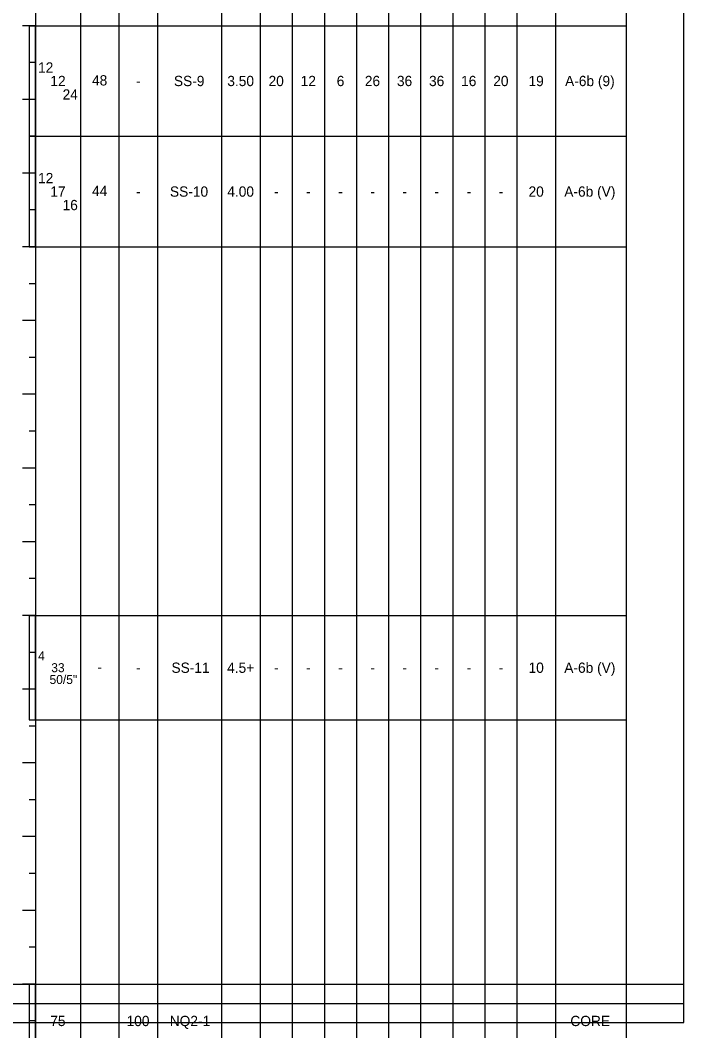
# Model space of a CAD drawing. Extents: x -0.01 to 0.83, y -0.77 to 1.27.
# Drawn here: x 0.403 to 0.833, y -0.03 to 0.625 of the extents above; entities that cross this region are included whole.
import ezdxf

# ---------------------------------------------------------------- set-up
doc = ezdxf.new("R2010")
doc.units = 0

msp = doc.modelspace()

# ---------------------------------------------------------------- linework, layer by layer
for points in [[(0, 0), (0.83333, 0), (0.83333, 1.275), (0, 1.275)], [(0, 0), (0.83333, 0), (0.83333, 1.275), (0, 1.275)], [(0, 0), (0.83333, 0), (0.83333, 1.275), (0, 1.275)], [(0, 0), (0.83333, 0), (0.83333, 1.275), (0, 1.275)], [(0, 0), (0.83333, 0), (0.83333, 1.275), (0, 1.275)], [(0.40833, 0.55008), (0.4125, 0.55008), (0.4125, 0.62183), (0.40833, 0.62183)], [(0.40833, 0.47833), (0.4125, 0.47833), (0.4125, 0.55008), (0.40833, 0.55008)], [(0.40833, 0.1714), (0.4125, 0.1714), (0.4125, 0.23917), (0.40833, 0.23917)], [(0.40833, -0.04783), (0.4125, -0.04783), (0.4125, 0), (0.40833, 0)]]:
    msp.add_lwpolyline(points, close=True)
for points in [[(0.4125, 1.22083), (0.4125, -0.76533)], [(0.4125, 1.22083), (0.4125, -0.76533)], [(0.44167, 1.22083), (0.44167, -0.76533)], [(0.46667, 1.22083), (0.46667, -0.76533)], [(0.49167, 1.22083), (0.49167, -0.76533)], [(0.53333, 1.22083), (0.53333, -0.76533)], [(0.55833, 1.22083), (0.55833, -0.76533)], [(0.6625, 1.22083), (0.6625, -0.76533)], [(0.725, 1.22083), (0.725, -0.76533)], [(0.75, 1.22083), (0.75, -0.76533)], [(0.75, 1.22083), (0.75, -0.76533)], [(0.79583, 1.22083), (0.79583, -0.76533)], [(0.57917, 1.20833), (0.57917, -0.76533)], [(0.6, 1.20833), (0.6, -0.76533)], [(0.62083, 1.20833), (0.62083, -0.76533)], [(0.64167, 1.20833), (0.64167, -0.76533)], [(0.68333, 1.20833), (0.68333, -0.76533)], [(0.70417, 1.20833), (0.70417, -0.76533)], [(0.725, 1.20833), (0.725, -0.76533)], [(0.4125, 0.62183), (0.40417, 0.62183)], [(0.40833, 0.62183), (0.40833, 0.55008)], [(0.40833, 0.62183), (0.4125, 0.62183)], [(0.4125, 0.62183), (0.40833, 0.62183)], [(0.4125, 0.62183), (0.44167, 0.62183)], [(0.44167, 0.62183), (0.46667, 0.62183)], [(0.46667, 0.62183), (0.49167, 0.62183)], [(0.49167, 0.62183), (0.53333, 0.62183)], [(0.53333, 0.62183), (0.55833, 0.62183)], [(0.55833, 0.62183), (0.57917, 0.62183)], [(0.57917, 0.62183), (0.6, 0.62183)], [(0.6, 0.62183), (0.62083, 0.62183)], [(0.62083, 0.62183), (0.64167, 0.62183)], [(0.64167, 0.62183), (0.6625, 0.62183)], [(0.6625, 0.62183), (0.68333, 0.62183)], [(0.68333, 0.62183), (0.70417, 0.62183)], [(0.70417, 0.62183), (0.725, 0.62183)], [(0.725, 0.62183), (0.75, 0.62183)], [(0.75, 0.62183), (0.79583, 0.62183)], [(0.4125, 0.59792), (0.40833, 0.59792)], [(0.4125, 0.574), (0.40417, 0.574)], [(0.4125, 0.574), (0.40833, 0.574)], [(0.40833, 0.55008), (0.4125, 0.55008)], [(0.40833, 0.55008), (0.40833, 0.47833)], [(0.40833, 0.55008), (0.4125, 0.55008)], [(0.4125, 0.55008), (0.40833, 0.55008)], [(0.4125, 0.55008), (0.44167, 0.55008)], [(0.44167, 0.55008), (0.46667, 0.55008)], [(0.46667, 0.55008), (0.49167, 0.55008)], [(0.49167, 0.55008), (0.53333, 0.55008)], [(0.53333, 0.55008), (0.55833, 0.55008)], [(0.55833, 0.55008), (0.57917, 0.55008)], [(0.57917, 0.55008), (0.6, 0.55008)], [(0.6, 0.55008), (0.62083, 0.55008)], [(0.62083, 0.55008), (0.64167, 0.55008)], [(0.64167, 0.55008), (0.6625, 0.55008)], [(0.6625, 0.55008), (0.68333, 0.55008)], [(0.68333, 0.55008), (0.70417, 0.55008)], [(0.70417, 0.55008), (0.725, 0.55008)], [(0.725, 0.55008), (0.75, 0.55008)], [(0.75, 0.55008), (0.79583, 0.55008)], [(0.4125, 0.52617), (0.40417, 0.52617)], [(0.4125, 0.52617), (0.40833, 0.52617)], [(0.4125, 0.50225), (0.40833, 0.50225)], [(0.4125, 0.47833), (0.40417, 0.47833)], [(0.40833, 0.47833), (0.4125, 0.47833)], [(0.4125, 0.47833), (0.40833, 0.47833)], [(0.4125, 0.47833), (0.44167, 0.47833)], [(0.44167, 0.47833), (0.46667, 0.47833)], [(0.46667, 0.47833), (0.49167, 0.47833)], [(0.49167, 0.47833), (0.53333, 0.47833)], [(0.53333, 0.47833), (0.55833, 0.47833)], [(0.55833, 0.47833), (0.57917, 0.47833)], [(0.57917, 0.47833), (0.6, 0.47833)], [(0.6, 0.47833), (0.62083, 0.47833)], [(0.62083, 0.47833), (0.64167, 0.47833)], [(0.64167, 0.47833), (0.6625, 0.47833)], [(0.6625, 0.47833), (0.68333, 0.47833)], [(0.68333, 0.47833), (0.70417, 0.47833)], [(0.70417, 0.47833), (0.725, 0.47833)], [(0.725, 0.47833), (0.75, 0.47833)], [(0.75, 0.47833), (0.79583, 0.47833)], [(0.4125, 0.45442), (0.40833, 0.45442)], [(0.4125, 0.4305), (0.40417, 0.4305)], [(0.4125, 0.4305), (0.40833, 0.4305)], [(0.4125, 0.40658), (0.40833, 0.40658)], [(0.4125, 0.38267), (0.40417, 0.38267)], [(0.4125, 0.38267), (0.40833, 0.38267)], [(0.4125, 0.35875), (0.40833, 0.35875)], [(0.4125, 0.33483), (0.40417, 0.33483)], [(0.4125, 0.33483), (0.40833, 0.33483)], [(0.4125, 0.31092), (0.40833, 0.31092)], [(0.4125, 0.287), (0.40417, 0.287)], [(0.4125, 0.287), (0.40833, 0.287)], [(0.4125, 0.26308), (0.40833, 0.26308)], [(0.4125, 0.23917), (0.40417, 0.23917)], [(0.40833, 0.23917), (0.40833, 0.1714)], [(0.40833, 0.23917), (0.4125, 0.23917)], [(0.4125, 0.23917), (0.40833, 0.23917)], [(0.4125, 0.23917), (0.44167, 0.23917)], [(0.44167, 0.23917), (0.46667, 0.23917)], [(0.46667, 0.23917), (0.49167, 0.23917)], [(0.49167, 0.23917), (0.53333, 0.23917)], [(0.53333, 0.23917), (0.55833, 0.23917)], [(0.55833, 0.23917), (0.57917, 0.23917)], [(0.57917, 0.23917), (0.6, 0.23917)], [(0.6, 0.23917), (0.62083, 0.23917)], [(0.62083, 0.23917), (0.64167, 0.23917)], [(0.64167, 0.23917), (0.6625, 0.23917)], [(0.6625, 0.23917), (0.68333, 0.23917)], [(0.68333, 0.23917), (0.70417, 0.23917)], [(0.70417, 0.23917), (0.725, 0.23917)], [(0.725, 0.23917), (0.75, 0.23917)], [(0.75, 0.23917), (0.79583, 0.23917)], [(0.4125, 0.21525), (0.40833, 0.21525)], [(0.4125, 0.19133), (0.40417, 0.19133)], [(0.4125, 0.19133), (0.40833, 0.19133)], [(0.40833, 0.1714), (0.4125, 0.1714)], [(0.4125, 0.1714), (0.44167, 0.1714)], [(0.44167, 0.1714), (0.46667, 0.1714)], [(0.46667, 0.1714), (0.49167, 0.1714)], [(0.49167, 0.1714), (0.53333, 0.1714)], [(0.53333, 0.1714), (0.55833, 0.1714)], [(0.55833, 0.1714), (0.57917, 0.1714)], [(0.57917, 0.1714), (0.6, 0.1714)], [(0.6, 0.1714), (0.62083, 0.1714)], [(0.62083, 0.1714), (0.64167, 0.1714)], [(0.64167, 0.1714), (0.6625, 0.1714)], [(0.6625, 0.1714), (0.68333, 0.1714)], [(0.68333, 0.1714), (0.70417, 0.1714)], [(0.70417, 0.1714), (0.725, 0.1714)], [(0.725, 0.1714), (0.75, 0.1714)], [(0.75, 0.1714), (0.79583, 0.1714)], [(0.4125, 0.16742), (0.40833, 0.16742)], [(0.4125, 0.1435), (0.40417, 0.1435)], [(0.4125, 0.1435), (0.40833, 0.1435)], [(0.4125, 0.11958), (0.40833, 0.11958)], [(0.4125, 0.09567), (0.40417, 0.09567)], [(0.4125, 0.09567), (0.40833, 0.09567)], [(0, 0.0875), (0, -0.025), (0.83333, -0.025), (0.83333, 0.0875)], [(0.4125, 0.07175), (0.40833, 0.07175)], [(0.4125, 0.04783), (0.40417, 0.04783)], [(0.4125, 0.04783), (0.40833, 0.04783)], [(0.4125, 0.02392), (0.40833, 0.02392)], [(0, 0), (0.83333, 0)], [(0.4125, 0), (0.40417, 0)], [(0.40833, 0), (0.40833, -0.04783)], [(0.40833, 0), (0.4125, 0)], [(0.4125, 0), (0.44167, 0)], [(0.44167, 0), (0.46667, 0)], [(0.46667, 0), (0.49167, 0)], [(0.49167, 0), (0.53333, 0)], [(0.53333, 0), (0.55833, 0)], [(0.55833, 0), (0.57917, 0)], [(0.57917, 0), (0.6, 0)], [(0.6, 0), (0.62083, 0)], [(0.62083, 0), (0.64167, 0)], [(0.64167, 0), (0.6625, 0)], [(0.6625, 0), (0.68333, 0)], [(0.68333, 0), (0.70417, 0)], [(0.70417, 0), (0.725, 0)], [(0.725, 0), (0.75, 0)], [(0.75, 0), (0.79583, 0)], [(0.4125, 0), (0.40833, 0)], [(0, -0.0125), (0.83333, -0.0125)], [(0.4125, -0.02392), (0.40833, -0.02392)]]:
    msp.add_lwpolyline(points)

# ---------------------------------------------------------------- texts
for s, height, p in [('12', 0.006667, (0.41417, 0.59137)), ('12', 0.006667, (0.42215, 0.58262)), ('48', 0.006667, (0.44919, 0.58304)), ('-', 0.00667, (0.47776, 0.58262)), ('SS-9', 0.006667, (0.50235, 0.58262)), ('3.50', 0.006667, (0.537, 0.58262)), ('20', 0.006667, (0.56379, 0.58262)), ('12', 0.006667, (0.58465, 0.58262)), ('6', 0.00667, (0.60804, 0.58262)), ('26', 0.006667, (0.62628, 0.58262)), ('36', 0.006667, (0.64712, 0.58262)), ('36', 0.006667, (0.66795, 0.58262)), ('16', 0.006667, (0.68878, 0.58262)), ('20', 0.006667, (0.70963, 0.58262)), ('19', 0.006667, (0.73253, 0.58262)), ('A-6b (9)', 0.006667, (0.75627, 0.58262)), ('24', 0.006667, (0.4301, 0.57387)), ('12', 0.006667, (0.41417, 0.51962)), ('17', 0.006667, (0.42212, 0.51087)), ('44', 0.006667, (0.44921, 0.51129)), ('-', 0.00667, (0.47776, 0.51087)), ('SS-10', 0.006667, (0.49978, 0.51087)), ('4.00', 0.006667, (0.537, 0.51087)), ('-', 0.00667, (0.56734, 0.51087)), ('-', 0.00667, (0.58818, 0.51087)), ('-', 0.00667, (0.60901, 0.51087)), ('-', 0.00667, (0.62984, 0.51087)), ('-', 0.00667, (0.65068, 0.51087)), ('-', 0.00667, (0.67151, 0.51087)), ('-', 0.00667, (0.69234, 0.51087)), ('-', 0.00667, (0.71318, 0.51087)), ('20', 0.006667, (0.73254, 0.51087)), ('A-6b (V)', 0.006667, (0.75575, 0.51087)), ('16', 0.006667, (0.43007, 0.50212)), ('4', 0.00583, (0.41417, 0.21002)), ('33', 0.005833, (0.42274, 0.20237)), ('-', 0.00667, (0.45276, 0.20237)), ('-', 0.00667, (0.47776, 0.20195)), ('SS-11', 0.006667, (0.50076, 0.20195)), ('4.5+', 0.006667, (0.5369, 0.20195)), ('-', 0.00667, (0.56734, 0.20195)), ('-', 0.00667, (0.58818, 0.20195)), ('-', 0.00667, (0.60901, 0.20195)), ('-', 0.00667, (0.62984, 0.20195)), ('-', 0.00667, (0.65068, 0.20195)), ('-', 0.00667, (0.67151, 0.20195)), ('-', 0.00667, (0.69234, 0.20195)), ('-', 0.00667, (0.71318, 0.20195)), ('10', 0.006667, (0.73254, 0.20195)), ('A-6b (V)', 0.006667, (0.75575, 0.20195)), ('50/5"', 0.005833, (0.42163, 0.19471)), ('75', 0.006667, (0.42209, -0.02725)), ('100', 0.006667, (0.47162, -0.02725)), ('NQ2-1', 0.006667, (0.49964, -0.02725)), ('CORE', 0.006667, (0.75971, -0.02725))]:
    msp.add_text(s, height=height).set_placement(p)

doc.saveas('drawing.dxf')
